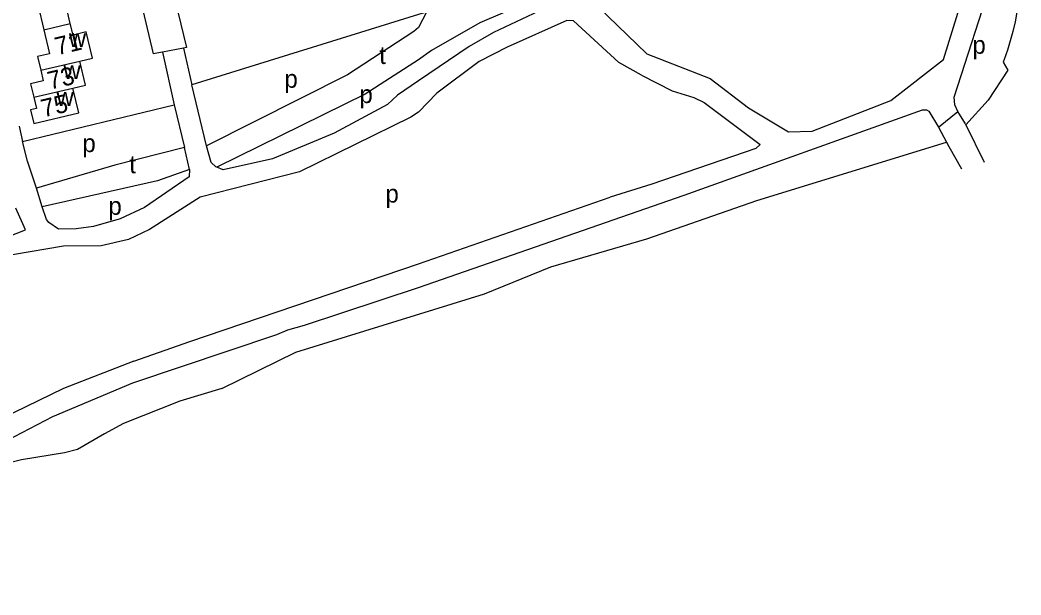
# Model space of a CAD drawing. Extents: x 157646 to 159241, y 379213 to 381217.
# Drawn here: x 159011 to 159234.6, y 380352.9 to 380481.3 of the extents above; entities that cross this region are included whole.
import ezdxf

# ---------------------------------------------------------------- set-up
doc = ezdxf.new("R2010")
doc.units = 0
for name, color, linetype in [('BLT_Basislijn', 7, 'Continuous'), ('BLT_Bebouwing', 7, 'Continuous'), ('BLT_Centroide', 7, 'Continuous'), ('BLT_Huisnummer', 7, 'Continuous'), ('BLT_Huisnummer_ tussenligend', 7, 'Continuous'), ('BLT_Onderverdeling_panden', 7, 'Continuous'), ('BLT_Vlakafsluiter', 7, 'Continuous')]:
    doc.layers.add(name, color=color, linetype=linetype)

msp = doc.modelspace()

# ---------------------------------------------------------------- linework, layer by layer
at = {"layer": 'BLT_Basislijn'}
for p, q in [((159033.59, 380503.67), (159040.77, 380473.78)), ((159042.84, 380474.16), (159040.77, 380473.78)), ((159042.84, 380474.16), (159045.45, 380462.42)), ((159047.51, 380475.03), (159049.37, 380466.86)), ((159149.8, 380469.04), (159156.66, 380465.5)), ((159052.65, 380453.23), (159049.37, 380466.86)), ((159011.6, 380454.21), (159045.45, 380462.42)), ((159045.45, 380462.42), (159047.73, 380452.85)), ((159222.14, 380458.16), (159220.45, 380460.92)), ((159010.79, 380457.61), (159011.6, 380454.21)), ((159216.14, 380457.38), (159217.92, 380454.03)), ((159222.14, 380458.16), (159222.24, 380457.94)), ((159048.85, 380447.93), (159047.73, 380452.85)), ((159217.92, 380454.03), (159218.46, 380453.07)), ((159218.46, 380453.07), (159221.28, 380448.1)), ((159054.96, 380448.44), (159054.75, 380448.53)), ((159152.12, 380444.64), (159142.82, 380441.78)), ((159015.97, 380439.63), (159014.7, 380443.74))]:
    msp.add_line(p, q, dxfattribs=at)
for points in [[(159221.43, 380486.08), (159222.67, 380490.41), (159222.26, 380501.35), (159222.04, 380501.77), (159217.81, 380503.41), (159214.08, 380504.44), (159179.96, 380496.96), (159151.63, 380488.82), (159140.13, 380484.3), (159151.01, 380473.8), (159165.12, 380468.24), (159173.74, 380461.75), (159182.65, 380456.36), (159187.9, 380456.5), (159205.5, 380463.37), (159217.26, 380472.5), (159221.43, 380486.08)], [(159220.45, 380460.92), (159219.78, 380462.39), (159219.65, 380464.07), (159228.32, 380491.1), (159229.81, 380494.9), (159234.21, 380496.12)], [(159234.5, 380496.21), (159234.56, 380494.01), (159234.54, 380491.82), (159234.44, 380489.62), (159234.26, 380487.43), (159234, 380485.25), (159233.66, 380483.08), (159233.25, 380480.92), (159232.75, 380478.78), (159232.18, 380476.66), (159231.53, 380474.56), (159230.8, 380472.49), (159230.6, 380471.94)], [(159045.01, 380488.45), (159048.22, 380475.16), (159047.51, 380475.03)], [(159131.62, 380488.18), (159129.43, 380487.46), (159113.71, 380480.68), (159102.93, 380474.49), (159100, 380472.43), (159088.12, 380464.78), (159054.96, 380448.44)], [(159131.62, 380488.18), (159132.2, 380486.05), (159129.4, 380484.46), (159116.76, 380478.53), (159111.36, 380475.39), (159100, 380467.74), (159095.35, 380464.55), (159093.06, 380462.45), (159081.21, 380456.03), (159067.43, 380450.3), (159056.4, 380447.86), (159054.96, 380448.44)], [(159101.79, 380483.11), (159100, 380482.56), (159049.37, 380466.86)], [(159101.79, 380483.11), (159100, 380479.65), (159098.97, 380478.78), (159084.17, 380469.08), (159052.65, 380453.23)], [(159149.8, 380469.04), (159144.73, 380471.83), (159134.61, 380481.15), (159133.12, 380481.25), (159119.82, 380475.3), (159113.55, 380472.09), (159104.07, 380464.96), (159100, 380460.76)], [(159047.51, 380475.03), (159042.84, 380474.16)], [(159230.6, 380471.94), (159231.59, 380470.14), (159227.2, 380463.45), (159222.24, 380457.94)], [(159156.66, 380465.5), (159161.53, 380464.01), (159163.79, 380462.94)], [(159163.79, 380462.94), (159176.32, 380453.51), (159175.37, 380452.62), (159152.12, 380444.64)], [(158967.79, 380362.49), (158972.23, 380365.12), (158989.6, 380377.12), (158996, 380381.16), (159018.34, 380392.75), (159036.19, 380400.28), (159068.37, 380411.08), (159070.83, 380412.13), (159074.58, 380413.16), (159100, 380421.59), (159159.32, 380442.21), (159212.56, 380461.26), (159213.48, 380461.3), (159213.98, 380460.98), (159216.14, 380457.38)], [(159100, 380460.76), (159098.33, 380459.6), (159073.45, 380447.42), (159051.24, 380441.76), (159039.94, 380434.55), (159035.23, 380432.33), (159029.12, 380430.89), (159020.71, 380430.83), (159009.3, 380428.89)], [(159222.24, 380457.94), (159226.3, 380449.57)], [(159014.7, 380443.74), (159012.65, 380449.77), (159011.6, 380454.21)], [(159047.73, 380452.85), (159032.17, 380448.91), (159014.7, 380443.74)], [(159054.75, 380448.53), (159053.72, 380449.51), (159052.65, 380453.23)], [(159056.09, 380399.02), (159072.61, 380407.15), (159114.76, 380420.17), (159129.53, 380426.23), (159150.98, 380432.46), (159175.6, 380440.99), (159217.92, 380454.03)], [(159048.85, 380447.93), (159048.82, 380446.33), (159038.84, 380439.49), (159033.39, 380436.95), (159027.43, 380435.22), (159023.52, 380434.68), (159019.64, 380434.61), (159017.45, 380436.1), (159016.94, 380436.78), (159015.97, 380439.63)], [(159048.85, 380447.93), (159041.69, 380445.44), (159015.97, 380439.63)], [(159036.41, 380405.12), (159048.92, 380409.51), (159100, 380426.89), (159142.82, 380441.78)], [(158940.56, 380399.93), (158944.61, 380395.96), (158947.84, 380395.21), (158951.39, 380395.83), (158952.44, 380396.37), (158989.64, 380425.58), (159012.27, 380434.43), (159010.1, 380439.28)], [(159036.41, 380405.12), (159020.76, 380399.01), (159001.25, 380389.59), (158988.68, 380382.53), (158970.68, 380369.83), (158955.53, 380361.41), (158954.03, 380360.73), (158953.74, 380360.97), (158952.74, 380370.76), (158949.02, 380388.03), (158978.82, 380413.04), (158988.84, 380419.76), (159002.2, 380426.28), (159009.3, 380428.89)], [(159056.09, 380399.02), (159046.73, 380396.21), (159034.13, 380391.18), (159029.91, 380388.94), (159023.85, 380385.43), (159020.98, 380384.65), (159011.37, 380383.11), (159003.76, 380381.2), (158997.06, 380375.22), (158982.23, 380362.35), (158973.65, 380354.35), (158967.65, 380349.55)]]:
    msp.add_lwpolyline(points, dxfattribs=at)
at = {"layer": 'BLT_Bebouwing'}
for points in [[(159022.25, 380480.53), (159021.64, 380483.12), (159024.49, 380483.8), (159023.12, 380489.6), (159020.19, 380488.91)], [(159011.54, 380486.86), (159012.26, 380483.8), (159015.06, 380484.46), (159016.33, 380479.12)], [(159024.35, 380472.17), (159027.18, 380472.84), (159025.8, 380478.66), (159022.86, 380477.96), (159022.25, 380480.53)], [(159016.33, 380479.12), (159017.59, 380473.78), (159014.92, 380473.15), (159015.64, 380470.11)], [(159022.83, 380466.13), (159025.62, 380466.79), (159024.35, 380472.17)], [(159015.64, 380470.11), (159016.2, 380467.77), (159013.38, 380467.1), (159014.1, 380464.06)], [(159014.1, 380464.06), (159014.7, 380461.56), (159013.39, 380461.25), (159014.11, 380458.22), (159024.14, 380460.59), (159022.83, 380466.13)]]:
    msp.add_lwpolyline(points, dxfattribs=at)
at = {"layer": 'BLT_Onderverdeling_panden'}
for p, q in [((159016.33, 380479.12), (159022.25, 380480.53)), ((159015.64, 380470.11), (159024.35, 380472.17)), ((159014.1, 380464.06), (159022.83, 380466.13))]:
    msp.add_line(p, q, dxfattribs=at)
at = {"layer": 'BLT_Vlakafsluiter'}
msp.add_line((159216.14, 380457.38), (159220.45, 380460.92), dxfattribs=at)

# ---------------------------------------------------------------- texts
at = {"layer": 'BLT_Centroide'}
for s, p in [('w', (159021.91, 380475.31)), ('t', (159091.26, 380471.5)), ('p', (159223.72, 380473.78)), ('w', (159020.71, 380468.12)), ('p', (159070.07, 380466.2)), ('w', (159019.16, 380462.16)), ('p', (159086.82, 380462.78)), ('p', (159024.95, 380451.83)), ('t', (159035.43, 380447.1)), ('p', (159092.63, 380440.55)), ('p', (159030.76, 380437.81))]:
    msp.add_text(s, height=4, dxfattribs=at).set_placement(p)
at = {"layer": 'BLT_Huisnummer'}
msp.add_text('75', height=4, rotation=13.3379, dxfattribs=at).set_placement((159016.23, 380459.55))
at = {"layer": 'BLT_Huisnummer_ tussenligend'}
for s, p in [('71', (159019.32, 380473.42)), ('73', (159017.7, 380465.75))]:
    msp.add_text(s, height=4, rotation=13.3455, dxfattribs=at).set_placement(p)

doc.saveas('drawing.dxf')
